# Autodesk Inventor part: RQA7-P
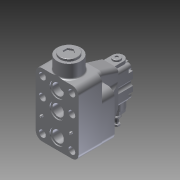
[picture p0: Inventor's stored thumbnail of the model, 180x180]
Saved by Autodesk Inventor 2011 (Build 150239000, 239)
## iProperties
Created: 2012-01
Part Number: RQA7-P
Document SubType Name: Modeling
Designer: khramov
Density: 1 g/cm^3
Author: khramov
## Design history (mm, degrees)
derived "RQA731.iam"
node "Твердое тело1"
node "0110264.ipt:1"
node "0571699.ipt:1"
sketch "0112483.ipt:1"
sketch "0550326.ipt:1"
sketch "0112484.ipt:1"
sketch "0571501.ipt:1"
sketch "0119296.ipt:1"
sketch "0530544.ipt:1"
sketch "0530329_ISO_24017___M8x40.ipt:1"
sketch "0530083_UNI_5931___M10x45.ipt:1"
sketch "0530083_UNI_5931___M10x45.ipt:2"
sketch "0530083_UNI_5931___M10x45.ipt:3"
sketch "0530083_UNI_5931___M10x45.ipt:4"
sketch "0550326_DIN_1481_6x16.ipt:1"
sketch "0550326_DIN_1481_6x16.ipt:2"
